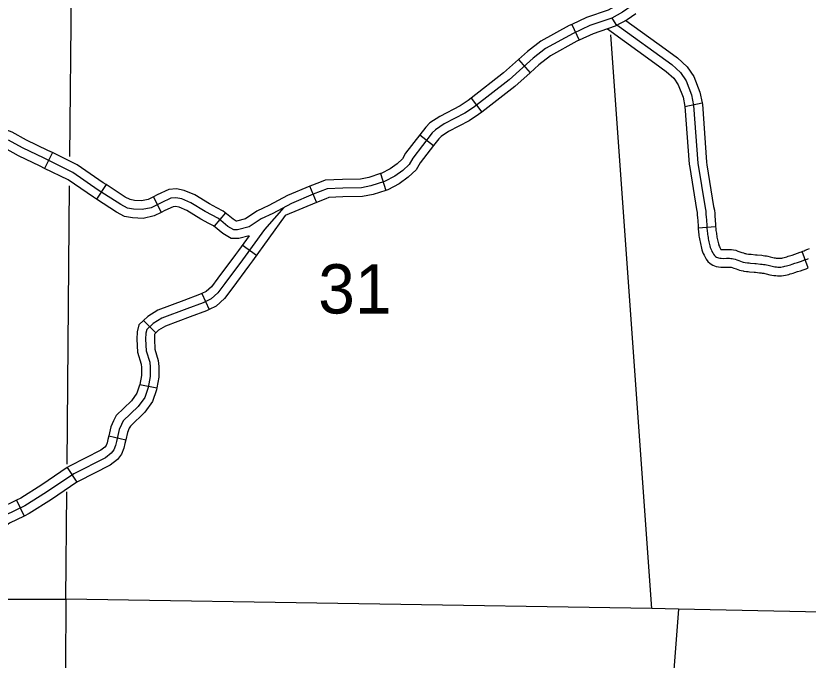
# Model space of a CAD drawing. Extents: x -19 to 366, y -4 to 359.
# Drawn here: x 133.386 to 134.672, y 197.983 to 199.029 of the extents above; entities that cross this region are included whole.
import ezdxf

# ---------------------------------------------------------------- set-up
doc = ezdxf.new("R2010")
doc.units = 0
for name, color, linetype in [('R_Alt Surface', 7, 'Continuous'), ('R_Axis', 7, 'Continuous'), ('R_Axis Annot', 7, 'Continuous'), ('R_ROW Annot', 7, 'Continuous'), ('Sheet Fence', 7, 'Continuous'), ('T_Indications', 7, 'Continuous')]:
    doc.layers.add(name, color=color, linetype=linetype)

msp = doc.modelspace()

# ---------------------------------------------------------------- linework, layer by layer
at = {"layer": 'R_Alt Surface'}
for points in [[(133.3488, 198.0824), (133.4674, 198.0826)], [(133.4674, 198.0826), (133.4635, 197.3027)]]:
    msp.add_lwpolyline(points, dxfattribs=at)
at = {"layer": 'R_Axis'}
for points in [[(133.474, 198.8006), (133.4764, 199.0694), (133.4762, 199.0827), (133.4706, 199.4781)], [(133.4694, 198.3011), (133.4735, 198.7529)], [(133.4674, 198.0826), (133.469, 198.2563)], [(139.2314, 198.0374), (138.3894, 198.0333), (138.3734, 198.0335), (137.3923, 198.046), (137.3636, 198.046), (136.3894, 198.0464), (136.3709, 198.0464), (135.3908, 198.0464), (135.3637, 198.047), (134.4615, 198.0663), (134.4184, 198.067), (133.4674, 198.0826)]]:
    msp.add_lwpolyline(points, dxfattribs=at)
at = {"layer": 'R_Axis Annot'}
for points in [[(134.4184, 198.067), (134.3519, 198.9979)], [(134.4615, 198.0663), (134.3841, 197.0611)]]:
    msp.add_lwpolyline(points, dxfattribs=at)
at = {"layer": 'R_ROW Annot'}
for p, q in [((134.2883, 199.0148), (134.3002, 198.989)), ((134.2018, 198.9577), (134.2208, 198.9365)), ((134.1251, 198.8951), (134.1425, 198.8727)), ((134.0417, 198.8357), (134.0642, 198.8183)), ((133.4454, 198.8068), (133.4328, 198.7813)), ((133.9781, 198.7727), (133.9866, 198.7456)), ((133.5325, 198.755), (133.5171, 198.7311)), ((133.8743, 198.7262), (133.8633, 198.7523)), ((133.6093, 198.7352), (133.622, 198.7098)), ((133.7264, 198.709), (133.7081, 198.6873)), ((133.7767, 198.64), (133.7537, 198.6566)), ((133.6878, 198.578), (133.6999, 198.5523)), ((133.5935, 198.5346), (133.6132, 198.5142)), ((133.5872, 198.4305), (133.6151, 198.4251)), ((133.537, 198.3475), (133.5646, 198.3409)), ((133.4696, 198.2958), (133.4854, 198.2721)), ((133.3873, 198.2428), (133.3995, 198.2172))]:
    msp.add_line(p, q, dxfattribs=at)
for points in [[(134.5678, 199.6774), (134.5989, 199.4588), (134.6024, 199.4475), (134.604, 199.4359), (134.6034, 199.4175), (134.5991, 199.4004), (134.589, 199.3767), (134.5593, 199.3208), (134.5233, 199.2575), (134.4604, 199.1384), (134.4258, 199.0786), (134.412, 199.0654), (134.3866, 199.0453), (134.3707, 199.0346), (134.3533, 199.0252)], [(134.3765, 199.0557), (134.3634, 199.0468), (134.3475, 199.0382), (134.3125, 199.026), (134.2883, 199.0148)], [(134.3533, 199.0252), (134.3178, 199.0128), (134.2904, 199.0002), (134.2459, 198.9759), (134.2256, 198.96), (134.1868, 198.9251), (134.1287, 198.8799), (134.1146, 198.8706), (134.0813, 198.8533), (134.0672, 198.8439), (134.062, 198.8388), (134.0306, 198.798)], [(134.3925, 199.0322), (134.3781, 199.0224), (134.359, 199.0122), (134.3231, 198.9996), (134.3002, 198.989)], [(134.2883, 199.0148), (134.284, 199.0129), (134.238, 198.9878), (134.2165, 198.9709), (134.2018, 198.9577)], [(134.3002, 198.989), (134.2968, 198.9875), (134.2537, 198.964), (134.2347, 198.9491), (134.2208, 198.9365)], [(134.2018, 198.9577), (134.1776, 198.936), (134.1251, 198.8951)], [(134.2208, 198.9365), (134.1959, 198.9142), (134.1425, 198.8727)], [(134.1251, 198.8951), (134.1204, 198.8915), (134.1074, 198.8828), (134.0741, 198.8655), (134.0582, 198.855), (134.0513, 198.8482), (134.0417, 198.8357)], [(134.1425, 198.8727), (134.137, 198.8684), (134.1219, 198.8583), (134.0885, 198.841), (134.0762, 198.8328), (134.0727, 198.8293), (134.0642, 198.8183)], [(133.4454, 198.8068), (133.4381, 198.8104), (133.4036, 198.8271), (133.3801, 198.8398), (133.3579, 198.8481), (133.3504, 198.8492)], [(134.0417, 198.8357), (134.0187, 198.8059), (134.0134, 198.7966), (134.005, 198.7888), (133.9936, 198.7806), (133.9788, 198.7729), (133.9781, 198.7727)], [(133.4328, 198.7813), (133.4256, 198.7849), (133.3907, 198.8018), (133.3683, 198.8139), (133.3507, 198.8204), (133.3462, 198.8211)], [(134.0306, 198.798), (134.0246, 198.7877), (134.0141, 198.7778), (134.001, 198.7685), (133.9843, 198.7598), (133.9625, 198.7529), (133.947, 198.7498), (133.9166, 198.7492), (133.8912, 198.748), (133.8688, 198.7393), (133.8334, 198.7244), (133.803, 198.7082), (133.7844, 198.6995), (133.7646, 198.6865), (133.7459, 198.6815), (133.7397, 198.6815), (133.7304, 198.6871), (133.7149, 198.7001), (133.6932, 198.7113), (133.6702, 198.7256), (133.6553, 198.7318), (133.646, 198.7337), (133.6379, 198.7331), (133.6218, 198.7256), (133.6057, 198.7175), (133.5914, 198.7144), (133.5771, 198.715), (133.5672, 198.7169), (133.5566, 198.7225), (133.52, 198.7461), (133.4784, 198.7747), (133.4319, 198.7976), (133.3971, 198.8144), (133.3742, 198.8268)], [(134.0642, 198.8183), (134.0424, 198.7901), (134.0359, 198.7788), (134.0231, 198.7668), (134.0085, 198.7563), (133.9897, 198.7466), (133.9866, 198.7456)], [(133.5325, 198.755), (133.5279, 198.7579), (133.4856, 198.7869), (133.4454, 198.8068)], [(133.5171, 198.7311), (133.5121, 198.7343), (133.4712, 198.7624), (133.4328, 198.7813)], [(133.9781, 198.7727), (133.959, 198.7667), (133.9455, 198.764), (133.9161, 198.7634), (133.8882, 198.762), (133.879, 198.7585)], [(133.6093, 198.7352), (133.6009, 198.731), (133.5902, 198.7287), (133.5787, 198.7292), (133.5719, 198.7305), (133.5638, 198.7348), (133.5325, 198.755)], [(133.879, 198.7585), (133.8635, 198.7524), (133.8273, 198.7372), (133.7967, 198.7209), (133.7873, 198.7165)], [(133.7126, 198.7173), (133.7002, 198.7237), (133.6767, 198.7383), (133.6595, 198.7455), (133.6469, 198.748), (133.6343, 198.747), (133.6156, 198.7384), (133.6093, 198.7352)], [(133.9866, 198.7456), (133.9661, 198.7391), (133.9486, 198.7356), (133.9171, 198.735), (133.8942, 198.7339), (133.8893, 198.732)], [(133.622, 198.7098), (133.6104, 198.704), (133.5926, 198.7002), (133.5755, 198.7009), (133.5624, 198.7033), (133.5494, 198.7102), (133.5171, 198.7311)], [(133.8893, 198.732), (133.8742, 198.7261), (133.8234, 198.7047)], [(133.821, 198.7178), (133.7896, 198.6821), (133.7542, 198.633), (133.7253, 198.5945), (133.714, 198.5796), (133.7031, 198.5695), (133.6899, 198.5633), (133.6638, 198.5535), (133.6229, 198.5383), (133.6089, 198.5298), (133.5988, 198.52), (133.5972, 198.5138), (133.5968, 198.504), (133.5976, 198.4853), (133.6034, 198.4666), (133.6042, 198.4588), (133.6042, 198.4436), (133.6007, 198.4257), (133.5953, 198.4097), (133.5847, 198.3949), (133.5606, 198.3716), (133.5575, 198.3657), (133.554, 198.3575), (133.5493, 198.338), (133.5477, 198.3314), (133.545, 198.3248), (133.5407, 198.319), (133.5318, 198.3119), (133.4804, 198.2858), (133.436, 198.2562), (133.4009, 198.2336), (133.3682, 198.218)], [(133.6996, 198.692), (133.6862, 198.699), (133.6637, 198.7129), (133.6511, 198.7182), (133.6451, 198.7194), (133.6416, 198.7191), (133.628, 198.7128), (133.622, 198.7098)], [(133.7873, 198.7165), (133.7775, 198.712), (133.7587, 198.6996), (133.7441, 198.6957), (133.7437, 198.6957), (133.7387, 198.6987), (133.7228, 198.712), (133.7126, 198.7173)], [(133.8234, 198.7047), (133.7704, 198.6313)], [(133.7646, 198.6718), (133.7478, 198.6673), (133.7358, 198.6673), (133.7221, 198.6755), (133.707, 198.6882), (133.6996, 198.692)], [(133.7646, 198.6718), (133.7474, 198.6479)], [(133.7474, 198.6479), (133.7427, 198.6414), (133.714, 198.603), (133.7035, 198.5892), (133.6951, 198.5814), (133.6878, 198.578)], [(133.7704, 198.6313), (133.7656, 198.6246), (133.7367, 198.5859), (133.7246, 198.5701), (133.7112, 198.5576), (133.6999, 198.5523)], [(133.6878, 198.578), (133.6844, 198.5764), (133.6588, 198.5668), (133.6167, 198.5512), (133.6002, 198.5411), (133.5935, 198.5346)], [(133.6999, 198.5523), (133.6954, 198.5502), (133.6688, 198.5402), (133.6291, 198.5255), (133.6176, 198.5185), (133.6132, 198.5142)], [(133.5935, 198.5346), (133.586, 198.5274), (133.5831, 198.5158), (133.5826, 198.504), (133.5835, 198.4829), (133.5894, 198.4638), (133.59, 198.4581), (133.59, 198.445), (133.5872, 198.4305)], [(133.6132, 198.5142), (133.6116, 198.5126), (133.6113, 198.5118), (133.611, 198.5041), (133.6117, 198.4878), (133.6174, 198.4695), (133.6184, 198.4596), (133.6184, 198.4423), (133.6151, 198.4251)], [(133.5872, 198.4305), (133.587, 198.4294), (133.5825, 198.4163), (133.5739, 198.4042), (133.5491, 198.3802), (133.5447, 198.3719), (133.5404, 198.362), (133.537, 198.3475)], [(133.6151, 198.4251), (133.6145, 198.422), (133.608, 198.4032), (133.5956, 198.3856), (133.5721, 198.3629), (133.5703, 198.3596), (133.5675, 198.353), (133.5646, 198.3409)], [(133.537, 198.3475), (133.5355, 198.3413), (133.5342, 198.3358), (133.5325, 198.3318), (133.5304, 198.3289), (133.5241, 198.324), (133.4732, 198.2981), (133.4696, 198.2958)], [(133.5646, 198.3409), (133.5631, 198.3348), (133.5613, 198.3271), (133.5575, 198.3178), (133.551, 198.309), (133.5394, 198.2999), (133.4875, 198.2735), (133.4854, 198.2721)], [(133.4696, 198.2958), (133.4282, 198.2681), (133.394, 198.246), (133.3873, 198.2428)], [(133.4854, 198.2721), (133.4438, 198.2443), (133.4079, 198.2212), (133.3995, 198.2172)], [(133.3873, 198.2428), (133.3607, 198.2302), (133.3432, 198.2165), (133.3349, 198.2015), (133.3285, 198.1818), (133.3228, 198.1595)], [(133.3995, 198.2172), (133.3757, 198.2059), (133.3652, 198.1977), (133.361, 198.1901), (133.3558, 198.1739), (133.3503, 198.1525)]]:
    msp.add_lwpolyline(points, dxfattribs=at)
at = {"layer": 'Sheet Fence'}
for points in [[(139.4406, 1.5315), (139.2511, 10.1473), (139.0608, 18.7633), (138.8699, 27.3793), (138.6784, 35.9956), (138.4861, 44.6119), (138.2932, 53.2285), (138.0997, 61.8451), (137.9055, 70.4619), (137.7106, 79.0789), (137.5151, 87.6959), (137.319, 96.3132), (137.1221, 104.9306), (136.9247, 113.5481), (136.7265, 122.1658), (136.5278, 130.7836), (136.3283, 139.4016), (136.1282, 148.0197), (135.9275, 156.6379), (135.7261, 165.2564), (135.5241, 173.8749), (135.3214, 182.4936), (135.1181, 191.1125), (134.9141, 199.7315), (134.7095, 208.3506), (134.5043, 216.9699), (134.2984, 225.5894), (134.0919, 234.209), (133.8847, 242.8288), (133.6769, 251.4487), (133.4685, 260.0687), (133.2594, 268.6889), (133.0497, 277.3093), (132.8393, 285.9298), (132.6283, 294.5504), (132.4167, 303.1713), (132.2044, 311.7922), (131.9916, 320.4133), (131.778, 329.0346), (131.5639, 337.656), (131.3491, 346.2776)], [(0, 198.1326), (7.1014, 198.137), (14.2028, 198.1503), (21.3042, 198.1724), (28.4055, 198.2034), (35.5068, 198.2433), (42.6081, 198.292), (49.7092, 198.3496), (56.8103, 198.4161), (63.9113, 198.4913), (71.0123, 198.5755), (78.1131, 198.6685), (85.2137, 198.7704), (92.3143, 198.8811), (99.4147, 199.0007), (106.5149, 199.1291), (113.615, 199.2664), (120.7149, 199.4126), (127.8146, 199.5676), (134.9141, 199.7315), (142.0135, 199.9042), (149.1125, 200.0858), (156.2114, 200.2762), (163.31, 200.4755), (170.4084, 200.6837), (177.5065, 200.9007), (184.6043, 201.1265), (191.7018, 201.3612), (198.799, 201.6048), (205.896, 201.8572), (212.9926, 202.1185), (220.0888, 202.3886), (227.1848, 202.6676), (234.2803, 202.9554), (241.3755, 203.2521), (248.4704, 203.5576), (255.5648, 203.872), (262.6589, 204.1952), (269.7525, 204.5273), (276.8457, 204.8682), (283.9385, 205.218), (291.0309, 205.5766), (298.1228, 205.9441), (305.2142, 206.3204), (312.3051, 206.7056), (319.3956, 207.0996), (326.4856, 207.5024), (333.5751, 207.9141), (340.664, 208.3347)], [(0, 189.5162), (7.1121, 189.5206), (14.2243, 189.5339), (21.3364, 189.556), (28.4484, 189.5869), (35.5605, 189.6267), (42.6725, 189.6754), (49.7844, 189.7329), (56.8962, 189.7992), (64.0079, 189.8744), (71.1196, 189.9584), (78.2311, 190.0512), (85.3425, 190.1529), (92.4538, 190.2635), (99.5649, 190.3829), (106.6759, 190.5111), (113.7867, 190.6482), (120.8974, 190.7941), (128.0078, 190.9489), (135.1181, 191.1125), (142.2282, 191.2849), (149.338, 191.4662), (156.4476, 191.6563), (163.5569, 191.8553), (170.666, 192.0631), (177.7749, 192.2798), (184.8835, 192.5053), (191.9917, 192.7396), (199.0997, 192.9828), (206.2074, 193.2348), (213.3147, 193.4956), (220.4218, 193.7653), (227.5285, 194.0438), (234.6348, 194.3312), (241.7408, 194.6274), (248.8464, 194.9324), (255.9516, 195.2463), (263.0564, 195.569), (270.1608, 195.9005), (277.2648, 196.2409), (284.3683, 196.5901), (291.4715, 196.9481), (298.5741, 197.315), (305.6763, 197.6907), (312.7781, 198.0753), (319.8793, 198.4686), (326.9801, 198.8708), (334.0804, 199.2818), (341.1801, 199.7017)]]:
    msp.add_spline(points, degree=3, dxfattribs=at)
at = {"layer": 'T_Indications'}
for p, q in [((134.4721, 198.8816), (134.4999, 198.8875)), ((134.4935, 198.685), (134.5218, 198.6869)), ((134.672, 198.6197), (134.6621, 198.6463))]:
    msp.add_line(p, q, dxfattribs=at)
for points in [[(134.3533, 199.0252), (134.3596, 199.0157), (134.4507, 198.9496), (134.4648, 198.9368), (134.474, 198.9235), (134.4826, 198.9008), (134.4862, 198.8835), (134.4931, 198.7896), (134.5047, 198.717), (134.5059, 198.7117), (134.5062, 198.707), (134.5065, 198.7022), (134.5069, 198.6975), (134.5075, 198.6881), (134.5077, 198.6856), (134.5078, 198.6834), (134.5081, 198.6809), (134.5083, 198.6787), (134.5086, 198.6765), (134.5089, 198.674), (134.5093, 198.6716), (134.5096, 198.6693), (134.51, 198.6669), (134.5105, 198.6646), (134.511, 198.6623), (134.5115, 198.66), (134.512, 198.6577), (134.5126, 198.6554), (134.5132, 198.6531), (134.514, 198.6509), (134.5149, 198.6488), (134.5159, 198.6465), (134.5172, 198.644), (134.5185, 198.6418), (134.52, 198.6399), (134.5216, 198.6383), (134.5234, 198.6372), (134.5265, 198.636), (134.5287, 198.6356), (134.5311, 198.6354), (134.5346, 198.6353), (134.5394, 198.6354), (134.5421, 198.6354), (134.5441, 198.6354), (134.5466, 198.6353), (134.5488, 198.635), (134.5509, 198.6346), (134.5533, 198.6338), (134.5563, 198.6327), (134.5596, 198.6316), (134.5623, 198.6307), (134.5648, 198.6298), (134.5668, 198.6292), (134.5699, 198.6286), (134.5737, 198.6281), (134.5761, 198.6279), (134.5782, 198.6277), (134.5856, 198.627), (134.5879, 198.6268), (134.5949, 198.6261), (134.5974, 198.6258), (134.5996, 198.6255), (134.6022, 198.6251), (134.6043, 198.6247), (134.6071, 198.6242), (134.6135, 198.6225), (134.6157, 198.6219), (134.6181, 198.6216), (134.6205, 198.6213), (134.6229, 198.6212), (134.6256, 198.6212), (134.6276, 198.6212), (134.6298, 198.6215), (134.6323, 198.6219), (134.6344, 198.6224), (134.6368, 198.6231), (134.639, 198.6237), (134.6414, 198.6244), (134.6435, 198.625), (134.6459, 198.6258), (134.6504, 198.6272), (134.6549, 198.6287), (134.6594, 198.6302), (134.6638, 198.6318), (134.6662, 198.6327), (134.6682, 198.6334), (134.6704, 198.6342), (134.6726, 198.6351)], [(134.3761, 199.0213), (134.4397, 198.9752)], [(134.3464, 199.0078), (134.423, 198.9522)], [(134.4397, 198.9752), (134.4597, 198.9607), (134.4755, 198.9462), (134.4866, 198.9301), (134.4963, 198.9048), (134.4999, 198.8875)], [(134.423, 198.9522), (134.4417, 198.9386), (134.454, 198.9274), (134.4613, 198.9168), (134.4689, 198.8968), (134.4721, 198.8816)], [(134.4721, 198.8816), (134.4721, 198.8815), (134.4789, 198.788), (134.4798, 198.7827)], [(134.4999, 198.8875), (134.5003, 198.8855), (134.5072, 198.7912), (134.5078, 198.7871)], [(134.4798, 198.7827), (134.4907, 198.7143), (134.4918, 198.7096), (134.492, 198.7059), (134.4924, 198.7012), (134.4927, 198.6965), (134.4933, 198.6871), (134.4935, 198.685)], [(134.5078, 198.7871), (134.5186, 198.7196), (134.52, 198.7137), (134.5204, 198.708), (134.5207, 198.7033), (134.5211, 198.6985), (134.5217, 198.689), (134.5218, 198.6869)], [(134.4935, 198.685), (134.4935, 198.6846), (134.4937, 198.6822), (134.4939, 198.6796), (134.4942, 198.677), (134.4945, 198.6746), (134.4948, 198.672), (134.4952, 198.6694), (134.4956, 198.667), (134.4961, 198.6644), (134.4966, 198.6619), (134.4971, 198.6594), (134.4976, 198.6568), (134.4982, 198.6543), (134.4989, 198.6518), (134.4997, 198.6489), (134.5007, 198.6459), (134.5018, 198.6432), (134.5031, 198.6404), (134.5047, 198.6372), (134.5067, 198.6339), (134.5093, 198.6304), (134.5128, 198.6271), (134.5172, 198.6243), (134.5226, 198.6223), (134.5267, 198.6215), (134.5305, 198.6212), (134.5345, 198.6211), (134.5396, 198.6212), (134.5421, 198.6212), (134.5437, 198.6212), (134.5455, 198.6211), (134.5464, 198.621), (134.5471, 198.6209), (134.5487, 198.6203), (134.5516, 198.6193), (134.555, 198.6181), (134.5577, 198.6172), (134.5606, 198.6162), (134.5635, 198.6154), (134.5668, 198.6148)], [(134.5218, 198.6869), (134.5219, 198.6866), (134.522, 198.6845), (134.5222, 198.6823), (134.5224, 198.6803), (134.5227, 198.6783), (134.523, 198.676), (134.5233, 198.6738), (134.5237, 198.6716), (134.524, 198.6695), (134.5244, 198.6674), (134.5249, 198.6652), (134.5253, 198.6632), (134.5258, 198.6611), (134.5263, 198.659), (134.5268, 198.6574), (134.5273, 198.6559), (134.5279, 198.6544), (134.5287, 198.6527), (134.5296, 198.6509), (134.5303, 198.6498), (134.5304, 198.6497), (134.5306, 198.6497), (134.5318, 198.6496), (134.5347, 198.6495), (134.5392, 198.6496), (134.542, 198.6496), (134.5445, 198.6496), (134.5478, 198.6494), (134.5511, 198.6491), (134.5546, 198.6483), (134.5579, 198.6472), (134.561, 198.6461), (134.5642, 198.645), (134.5669, 198.6441), (134.569, 198.6434), (134.5701, 198.6431), (134.5721, 198.6427)], [(134.6621, 198.6463), (134.6632, 198.6467), (134.6653, 198.6475), (134.6673, 198.6483), (134.6716, 198.65), (134.6741, 198.6511)], [(134.5721, 198.6427), (134.5722, 198.6427), (134.5754, 198.6422), (134.5776, 198.642), (134.5795, 198.6418), (134.5868, 198.6412), (134.5894, 198.6409), (134.5966, 198.6402), (134.5992, 198.6398), (134.6016, 198.6395), (134.6043, 198.6391), (134.6068, 198.6387), (134.6103, 198.638), (134.617, 198.6362), (134.6184, 198.6359), (134.6199, 198.6357), (134.6216, 198.6355), (134.6234, 198.6354), (134.6254, 198.6354), (134.6265, 198.6354), (134.6277, 198.6355), (134.6293, 198.6358), (134.631, 198.6362), (134.6332, 198.6368), (134.6351, 198.6373), (134.6373, 198.638), (134.6393, 198.6386), (134.6416, 198.6393), (134.646, 198.6407), (134.6504, 198.6421), (134.6547, 198.6436), (134.659, 198.6452), (134.6613, 198.646), (134.6621, 198.6463)], [(134.5668, 198.6148), (134.5676, 198.6146), (134.5719, 198.614), (134.5747, 198.6137), (134.5769, 198.6135), (134.5843, 198.6129), (134.5865, 198.6127), (134.5933, 198.6119), (134.5956, 198.6117), (134.5976, 198.6114), (134.6, 198.611), (134.6018, 198.6107), (134.6039, 198.6104), (134.61, 198.6087), (134.6131, 198.608), (134.6164, 198.6075), (134.6193, 198.6072), (134.6223, 198.607), (134.6257, 198.6069), (134.6286, 198.6071), (134.6319, 198.6074), (134.6352, 198.608), (134.6378, 198.6087), (134.6405, 198.6093), (134.6429, 198.61), (134.6454, 198.6107), (134.6477, 198.6114), (134.6502, 198.6122), (134.6548, 198.6137), (134.6594, 198.6152), (134.664, 198.6168), (134.6686, 198.6184), (134.6711, 198.6193), (134.672, 198.6197)]]:
    msp.add_lwpolyline(points, dxfattribs=at)

# ---------------------------------------------------------------- texts
at = {"layer": 'R_Axis Annot'}
msp.add_text('31', height=0.08, dxfattribs=at).set_placement((133.8769, 198.5458))

doc.saveas('drawing.dxf')
